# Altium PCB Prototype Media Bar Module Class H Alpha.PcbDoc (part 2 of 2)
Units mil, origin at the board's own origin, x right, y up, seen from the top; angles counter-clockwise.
Board outline 436.13 x 1831.8 mil, 6 copper layers (Component Side, Ground Plane (GND), Inner Layer 1, Inner Layer 2, Power Plane (VCC), Solder Side), stack 51.068 mil thick; 139 components, 72 nets, 710 pads, 418 vias.
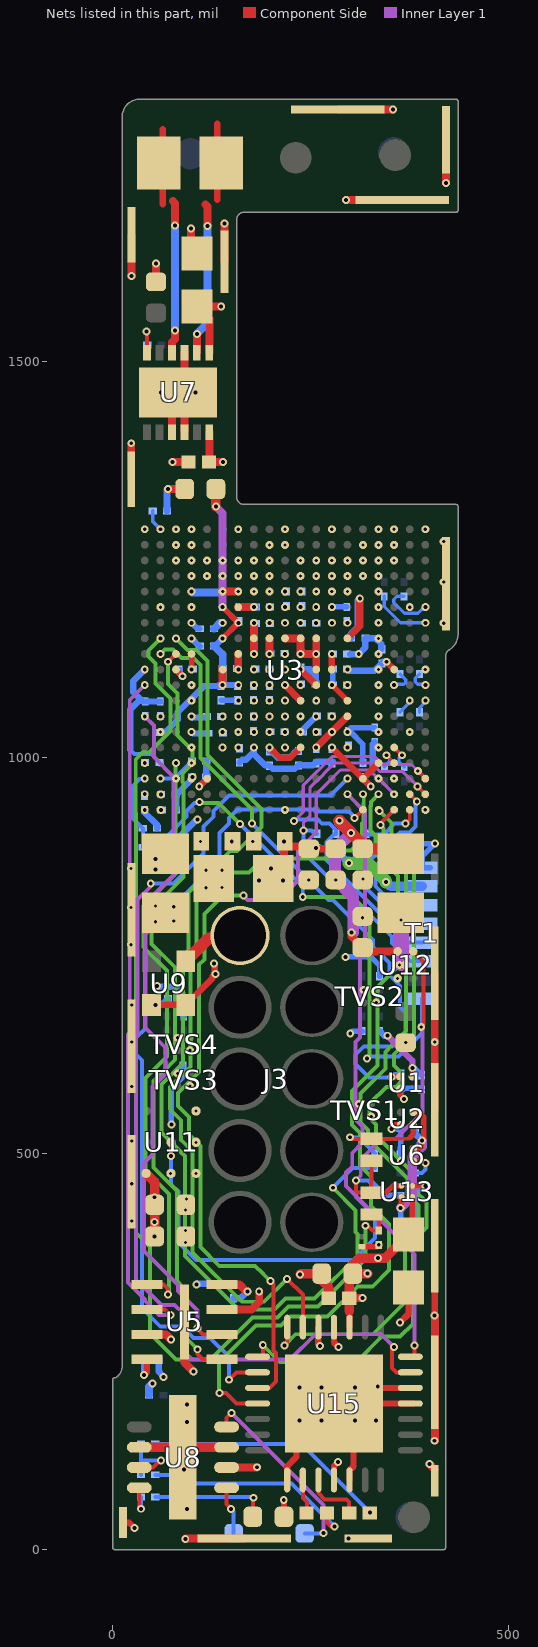
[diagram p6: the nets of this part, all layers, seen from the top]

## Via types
v1: diameter 10, hole 5, Component Side to Solder Side, tented both sides, 279 vias
v2: diameter 10, hole 4, Component Side to Ground Plane (GND), tented both sides, 132 vias
v3: diameter 10, hole 4, Ground Plane (GND) to Inner Layer 1, tented both sides, 6 vias
v4: diameter 10, hole 5, Component Side to Solder Side, 1 vias

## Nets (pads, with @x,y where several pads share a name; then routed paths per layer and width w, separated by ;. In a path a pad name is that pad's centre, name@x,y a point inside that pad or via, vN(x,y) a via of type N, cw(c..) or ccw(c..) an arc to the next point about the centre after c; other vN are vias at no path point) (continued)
GND: C1.1 C2.1 C3.1 C4.1 C5.1 C6.1 C7.1 C8.1 C12.2 C13.2 C14.2 C15.2 C16.1 C17.2 C18.1 C19.1 C20.1 C21.1 C22.1 C23.1 C24.1 C25.1 C26.1 C27.1 C28.1 C29.1 C30.1 C31.1 C32.1 C33.1 C34.1 C35.1 C36.1 C37.1 C38.1 C39.1 C40.1 C41.1 C42.1 C43.1 C44.1 C47.1 C50.1 C51.1 C52.1 C58.1 C59.1 C60.1 C61.1 C62.1 C63.1 C64.1 C65.1 C66.1 C67.1 C68.1 C69.1 C70.1 C71.1 C72.1 C73.1 C77.1 C78.1 C81.1 C82.1 C94.1 C95.1 J3.10 pad.2@12.74,34.06 pad.2@23.38,1351.87 pad.2@23.62,464.31 pad.2@23.62,635.96 pad.2@23.62,808.01 pad.2@23.62,1660.49 pad.2@141.1,1626.52 pad.2@165.9,13.93 pad.2@284.41,1818.88 pad.2@322.99,13.93 pad.2@365.51,1704.7 pad.2@406.69,86.83 pad.2@406.69,211.16 pad.2@406.69,384 pad.2@406.69,555.65 pad.2@406.69,727.7 pad.2@420.64,1219.86 pad.2@421.02,1780.45 R1.1 R2.1 R5.2 R20.1 R21.2 R23.2 R24.2 R25.2 R30.2 R32.2 R33.2 R37.2 R62.2 R67.2 R68.2 T1.1 TVS1.A2 TVS1.B1 TVS2.A2 TVS2.B1 TVS3.A2 TVS3.B1 TVS4.A2 TVS4.B1 TVS7.2 U1.B1 U2.B1 U3.A1 U3.A10 U3.A19 U3.C3 U3.C4 U3.C16 U3.C17 U3.D16 U3.E4 U3.E10 U3.E12 U3.E16 U3.F2 U3.F4 U3.F6 U3.F9 U3.F11 U3.F13 U3.F16 U3.F18 U3.G4 U3.G8 U3.G9 U3.G11 U3.G12 U3.G16 U3.H4 U3.H6 U3.H8 U3.H10 U3.H12 U3.H13 U3.H16 U3.J4 U3.J7 U3.J9 U3.J11 U3.J16 U3.K1 U3.K4 U3.K8 U3.K10 U3.K12 U3.K13 U3.K16 U3.K19 U3.L4 U3.L8 U3.L9 U3.L11 U3.L12 U3.L13 U3.L16 U3.M4 U3.M8 U3.M9 U3.M10 U3.M11 U3.M12 U3.M16 U3.N4 U3.N7 U3.N8 U3.N12 U3.N16 U3.P2 U3.P4 U3.P7 U3.P8 U3.P12 U3.P13 U3.P16 U3.P18 U3.R4 U3.R6 U3.R7 U3.R8 U3.R9 U3.R10 U3.R11 U3.R12 U3.R13 U3.R14 U3.R16 U3.T4 U3.T5 U3.T6 U3.T7 U3.T8 U3.T9 U3.T11 U3.T12 U3.T13 U3.T14 U3.T15 U3.T16 U3.U3 U3.U4 U3.U5 U3.U6 U3.U7 U3.U8 U3.U9 U3.U11 U3.U12 U3.U13 U3.U14 U3.U15 U3.U16 U3.U17 U3.V3 U3.V4 U3.V5 U3.V10 U3.V11 U3.V16 U3.V17 U3.W1 U3.W3 U3.W4 U3.W7 U3.W10 U3.W13 U3.W16 U3.W17 U3.W19 U5.4 U5.9 U6.B1 U7.3 U7.9 U7.10 U7.13 U8.2 U8.7 U8.9 U9.2 U11.B1 U11.C1 U11.C2 U11.C3 U12.A3 U13.B1 U15.8 U15.12 U15.18 U15.19 U15.25 U15.29 | length 3762.9
  Component Side w7: v1(99.51,1111.49) U3.L16@99.51,1131.18 ; U3.J7@276.48,1092 v1(276.67,1091.81) U3.H6@296.36,1072.12 ; TVS7.2@315,382.7 333.76,382.7 v2(336,384.94) ; v1(351.93,531) 357.55,536.62 U2.B1@363.74,536.62 ; U1.B1@362.74,581.62 362.74,574.26 v1(368,569) ; U13.B1@378.51,459.38 v1@394.62,459.38
  Component Side w8: pad.2@12.74,34.06 21.05,34.06 v1(27.62,27.49) ; v1(39.62,220.6) 43.37,224.36 U5.4@43.37,240.25 ; v1(216,62.45) 216.3,62.14 C47.1@216.3,41.49 ; U15.8@220.36,88.04 220.36,105.36 232,117 232,132.07 U15.29@284.42,184.49 ; U15.25@279.42,280.95 279.42,261.58 v1(285,256) ; U15.12@299.1,88.04 299.1,100 304.1,105 304.1,164.81 U15.29@284.42,184.49 ; v1(363,287) 373.62,297.62 C95.1@373.62,331.03 ; U15.18@365.93,184.49 U15.18@375.87,184.49 ; U15.18@381.19,184.49 U15.18@375.87,184.49 ; U15.19@381.19,204.18 U15.19@375.87,204.18 304.1,204.18 U15.29@284.42,184.49 ; pad.2@406.69,384 406.69,295.74 406.94,295.49 407,295.42 pad.2@407,211.16 ; U15.29@284.42,184.49 U15.18@375.87,184.49
  Component Side w10: pad.2@23.38,1351.87 v1(23.38,1397.26) ; v1(23.62,1608.49) pad.2@23.62,1660.49 ; C50.1@54.62,1601.18 v1(54.62,1624.49) ; v1(69.62,1339.49) C60.1@90.93,1339.49 ; U7.9@74.74,1411.3 74.74,1453.62 U7.13@82.62,1461.49 ; v1(75.62,1373.49) C77.1@95.63,1373.49 ; U7.10@90.49,1411.3 90.49,1453.62 U7.13@82.62,1461.49 ; U7.3@90.49,1511.69 90.49,1469.37 U7.13@82.62,1461.49 ; U5.9@90.62,287.49 90.62,236.38 v1(102,225) ; v1@91.93,13.49 92.37,13.93 pad.2@165.9,13.93 pad.2@166.22,13.93 ; v1(98.62,1668.49) 98.62,1647.96 C52.1@109.62,1636.96 ; v2(138.88,1209.92) v2(158.56,1209.92) ; pad.2@141.1,1626.52 v1(141.1,1675.01) ; v1(158.56,1111.49) U3.L13@158.56,1131.18 ; U3.P13@158.56,1190.23 v1(178.25,1190.23) ; v1(178.25,1131.18) U3.M12@178.25,1150.86 v1(178.25,1170.55) ; v1(197.93,1131.18) U3.M11@197.93,1150.86 ; U3.M10@217.62,1150.86 U3.M9@237.3,1150.86 v1(237.3,1131.18) v1(256.99,1131.18) ; U3.K8@256.99,1111.49 v1(256.99,1131.18) ; U3.M8@256.99,1150.86 v1(256.99,1131.18) ; pad.2@284.41,1818.88 v1(354,1818.88) ; v1(294.83,1704.7) pad.2@365.51,1704.7 ; v1(400,108) pad.2@406.69,101.31 ; pad.2@406.69,555.96 pad.2@406.69,555.65 v2(406.69,641) pad.2@406.69,727.7 ; v1@406.93,137.49 407,137.56 407,211.16 406.94,211.23 v1@406.94,295.49 ; v1(421.02,1726.13) pad.2@421.02,1780.45
  Component Side w12: U8.2@29.14,129.29 U8.2@33.5,129.29 U8.2@39.5,129.29 ; U8.2@39.7,129.49 U8.2@39.5,129.29 ; U8.7@137.14,129.29 U8.7@143.74,129.29 ; U8.7@149.53,129.49 U8.7@149.74,129.29 ; U8.7@150.05,129.29 U8.7@149.74,129.29 ; v1@236.93,347.49 237.93,348.49 C43.1@263.93,348.49 264.25,348.49 264.25,339.56 272.94,330.87 C42.1@272.94,317.5 ; U8.2@39.5,129.29 75.82,129.29 U8.9@88.62,116.49 101.41,129.29 U8.7@143.74,129.29 ; U8.7@143.74,129.29 U8.7@149.74,129.29
  Component Side w15: U9.2@92.27,743.05 121.22,772 157.12,772 J3.10@160.76,775.64
  Solder Side w5: 22,1010 27.22,1004.78 48.66,1004.78 59.06,994.39 R30.2@59.06,994
  Solder Side w7: v1(74,537) 74,582.38 88.62,597 R67.2@88.62,611.44 ; v1(99.51,1170.55) 107.05,1163 C28.1@109.94,1163 ; C34.1@136.8,1072.64 C5.1@157.3,1072.64 ; v1(276.67,1091.81) 278,1093.13 278,1111.94 C6.1@277.94,1112 ; v1(276.67,1190.23) 276.99,1190.55 C58.1@295.62,1190.55 ; v1(293.82,748.47) 313.23,748.5 ; v1(300,652) 302.94,654.94 R37.2@315,654.94 ; 313.26,748.47 320.97,748.47 ; C35.1@316,993.65 316,1017 299.45,1033.55 296.62,1033.55 301.13,1038.06 C17.2@331,1038.06 ; 321,748.5 326.25,748.5 337,737.75 R62.2@337,724.06 ; v1@352.42,531.49 C32.1@363.56,531.49 ; C39.1@363.56,499.49 C32.1@363.56,531.49 ; C32.1@363.56,532.44 C32.1@363.56,531.49 ; R32.2@367.06,890 385.49,890 387.22,891.72 v1(407,891.72) 390.62,875.34 T1.1@390.62,861.17 T1.1@401.17,861.17 ; v1(368,569) 364,573 R2.1@364,582.94 388,582.94 C31.1@390,580.94 ; R5.2@381.67,447.49 381.67,448.68 392.05,459.06 392.11,459 v1(395,459)
  Solder Side w8: 22,1010 22,1061 35,1074 ; v1@39.88,220.6 C13.2@39.88,239.49 ; R24.2@40,933.94 40,931.12 56.06,915.07 C14.2@56.06,911 ; v1(40.45,1111.49) 26,1097.04 26,1083 35,1074 ; v1(56,712) 56,711 80,711 88.06,702.94 C8.1@88.06,696 88.06,675.11 R68.2@89.62,673.55 ; R21.2@60,1071.06 R20.1@41,1071.06 37.94,1071.06 35,1074 ; R25.2@80.06,934 80.06,953 C44.1@99.94,972.89 ; v1(99.45,1032.82) 101.66,1030.6 C15.2@115.94,1030.6 ; v1(99.51,1150.86) 109.37,1141 C70.1@109.94,1141 ; v1@100.94,1051 117.95,1051 C18.1@118.94,1052 ; v1(106,335) v1@106.55,335 ; v1@106.55,335.55 C12.2@152.62,335.55 C12.2@152.93,335.55 ; C67.1@160,993.94 163.77,997.72 168.28,997.72 178.25,1007.68 ; v1(178.25,1013.07) 178.25,1007.68 ; v1(178.25,1190.23) 180.3,1190.23 C29.1@180.56,1190.49 ; C73.1@240.14,1032.6 240.14,1035.59 v1(256.99,1052.44) ; C26.1@277.43,994.94 257,994.94 252.5,990.44 C51.1@234.5,990.44 230.06,986 202.14,986 197.9,990.24 192.76,990.24 178.25,1004.75 178.25,1007.68 ; C7.1@300.06,1131 v1(310.68,1131) 319.06,1139.37 C24.1@319.06,1151.1 331.9,1151.1 339,1144 C62.1@339,1137.06 ; C94.1@381.67,413.49 R5.2@381.67,447.49
  Solder Side w9: R33.2@68.67,1311.49 v1@68.67,1338.55
  Solder Side w10: v1(99.51,1209.92) 100.88,1208.55 C71.1@138.62,1208.55 ; C69.1@159.62,1190.55 180.51,1190.55 C29.1@180.56,1190.49
  other v1: 91.62,13.49 298,14 94,51 90,101 406.62,137.49 93.68,161 235.68,163 263.68,163 305.68,163 332.68,163 94,183 236,205 263.68,205 305.68,205 334.68,206 406.62,295.49 236.62,347.49 40.45,934.33 101,976 217.62,1013.07 197.93,1032.75 296.36,1032.75 99.51,1052.44 178.25,1052.44 197.93,1052.44 158.56,1072.12 178.25,1072.12 217.62,1072.12 197.93,1091.81 237.3,1091.81 178.25,1111.49 217.62,1111.49 256.99,1170.55 276.67,1170.55 256.99,1190.23 217.62,1209.92 237.3,1209.92 60.96,1461.49 104.27,1461.49
  other v2: 92,388 92,403 24,415 92,429 93,443 24,462 73,475 105.11,475.12 363.74,490.62 105.11,514.12 24,516 326.49,547.13 105.11,554.12 310.74,562.87 24,585 97.49,585.62 81.74,601.37 97.49,630.62 370,640.32 24,641 81.74,646.37 24,688 332.72,690.81 316.97,706.56 359.77,721.45 23,764 54,793 77,794 315.62,798 23,811 77,812 54,813 117.88,835.88 138,836 247.62,845.81 281.62,845.81 316.16,846.84 118,858 138,858 23,860 110.93,894.49 176.93,894.49 217.62,934.33 394.78,934.33 79.82,973.7 335.73,973.7 355.41,973.7 99.51,993.38 99.51,1013.07 335.73,1013.07 60.14,1032.75 158.56,1032.75 237.3,1032.75 335.73,1032.75 375.1,1032.75 237.3,1052.44 335.73,1052.44 99.51,1072.12 256.99,1072.12 335.73,1072.12 99.51,1091.81 335.73,1091.81 335.73,1111.49 394.78,1111.49 335.73,1131.18 335.73,1150.86 335.73,1170.55 418,1170 60.14,1190.23 99.51,1190.23 335.73,1190.23 375.1,1190.23 178.25,1209.92 197.93,1209.92 256.99,1209.92 276.67,1209.92 296.36,1209.92 335.73,1209.92 418,1222 99.51,1229.6 119.19,1229.6 138.88,1229.6 158.56,1229.6 178.25,1229.6 197.93,1229.6 237.3,1229.6 256.99,1229.6 276.67,1229.6 296.36,1229.6 316.04,1229.6 335.73,1229.6 79.82,1249.29 99.51,1249.29 119.19,1249.29 138.88,1249.29 158.56,1249.29 178.25,1249.29 197.93,1249.29 237.3,1249.29 256.99,1249.29 276.67,1249.29 296.36,1249.29 316.04,1249.29 335.73,1249.29 355.41,1249.29 79.82,1268.97 99.51,1268.97 197.93,1268.97 217.62,1268.97 316.04,1268.97 335.73,1268.97 355.41,1268.97 418,1273 40.45,1288.66 79.82,1288.66 99.51,1288.66 158.56,1288.66 217.62,1288.66 276.67,1288.66 335.73,1288.66 355.41,1288.66 394.78,1288.66
INITN: R26.1 U3.C18 | length 49
  Solder Side w5: v4(60.14,973.7) 77.7,973.7 88,984 ; 88,984.05 R26.1@99.94,996
LOUT: C45.2 U15.9 | length 43.8
  Component Side w5: U15.9@240.05,88.04 240.05,65.32 245.36,60 C45.2@245.36,46.41
NetC45_1: C45.1 R19.1 | length 277.3
  Component Side w5: C45.1@270.92,45.99 270.92,45.68 C45.1@270.61,45.99 270.61,34.07 275.68,29 v1(280,29)
  Solder Side w5: R19.1@53.99,94.49 72.93,94.49 83.93,83.49 225.51,83.49 v1(280,29)
NetC46_1: C46.1 R3.1 | length 306.8
  Solder Side w5: R3.1@53.99,133.49 238.51,133.49 v1(325,47)
NetC47_2: C47.2 R4.1 | length 148.6
  Component Side w5: C47.2@177.25,41.49 177.25,64.81 v1@177.93,65.49
  Solder Side w5: R4.1@53.99,66.49 176.93,66.49 v1@177.93,65.49
  other v1: 177.62,65.49
NetL5_1: L5.1 U12.B2 | length 62.1
  Component Side w10: v2(362,738.49) U12.B2@369.62,738.49
  Inner Layer 1 w20: v3@364,740.49 v3(364,795)
  other v2: 364,795
  other v3: 362,738.49
NetL6_1: L6.1 U7.2 | length 289.9
  Component Side w8: 132,1705 132,1801
  Component Side w10: U7.2@106.24,1511.69 v1(106.24,1535.11) ; 117,1699 119.62,1696.38 v1(119.62,1671.49)
  Solder Side w10: v1(106.24,1535.11) 119.62,1548.49 119.62,1602 v1(119.62,1671.49)
NetL6_2: L6.2 U7.4 | length 289
  Component Side w8: 63,1699 63,1794
  Component Side w10: U7.4@74.74,1511.69 74.74,1524.85 78.62,1528.72 v1(78.62,1539.49) ; 76,1703 78.62,1700.38 v1(78.62,1672.49)
  Solder Side w10: v1(78.62,1539.49) v1(78.62,1672.49)
NetR3_2: R3.2 R19.2 U8.3 | length 89
  Component Side w5: U8.3@39.81,103.7 51,103.7 59.8,112.49 v1(61,112.49)
  Solder Side w5: R19.2@35.88,94.49 35.88,112.49 ; R3.2@35.88,133.49 35.88,112.49 ; v1(61,112.49) 35.88,112.49
NetR4_2: R4.2 U8.4 | length 42.5
  Component Side w5: U8.4@33.5,78.11 33.5,53.92 v1@35.88,51.55
  Solder Side w5: v1@35.88,51.55 R4.2@35.88,66.49
  other v1: 35.56,51.55
NetR21_1: R21.1 U3.G18
  other v1: 60.14,1052.44
NetR23_1: R23.1 U3.B18
  other v1: 61,953.82
NetR24_1: R24.1 U3.B19
  other v1: 40.45,954.01
NetR25_1: R25.1 U3.A18
  other v1: 61,933.82
NetR30_1: R30.1 U3.D19
  other v1: 40.45,993.38
NetR33_1: R33.1 U3.W18 | length 26.8
  Solder Side w5: R33.1@50.56,1311.49 50.56,1298.23 v1(60.14,1288.66)
NetR35_1: R35.1 U6.B2 | length 39.8
  Component Side w7: U6.B2@379.49,490.62 392.38,490.62 v1(395,488)
  Solder Side w5: R35.1@381.67,475.49 390.49,475.49 395,480 v1(395,488)
NetR39_2: R39.2 U7.6 | length 44.5
  Component Side w5: v1(42.62,1538.49) 43.25,1537.86 U7.6@43.25,1511.69
  Solder Side w5: v1(42.62,1538.49) 43.56,1537.55 R39.2@43.56,1521.49
NetU3_A3: U3.A3 U15.28 | length 896.2
  Component Side w5: v1(217,258) 220.36,261.36 U15.28@220.36,280.95 ; v1@337.04,915.96 U3.A3@355.41,934.33
  Inner Layer 2 w5: v1(217,258) 231,272 328.62,272 369,312.38 369,394 386,411 386,434.74 372,448.74 372,468.86 322.28,518.58 322.28,530.1 313,539.38 313,575.94 344.34,607.28 344.34,628.66 352.84,637.16 370.5,654.82 370.5,665 370.5,858.5 342.12,886.88 342.12,910.88
  other v1: 338,915
NetU3_A4: U3.A4 U15.1 | length 971.9
  Component Side w5: U15.1@189.49,245.08 v1(189.49,258.49)
  Inner Layer 2 w5: v1(189.49,258.49) 210.98,237 307.77,237 339.77,269 363,269 379,285 379,389.86 396,406.86 396,439 382,453 382,473 332.28,522.72 332.28,537.04 324.5,544.82 324.5,563.5 345.5,584.5 357.43,584.5 364.5,591.57 364.5,602.18 355.42,611.26 355.42,625.6 380.5,650.68 380.5,680 380.5,862.64 352.12,891.02 352.12,917.96 v1(337.18,932.91)
NetU3_A5: U3.A5 U15.2 | length 1063.8
  Component Side w5: v1@146.93,214.49 156.3,223.86 U15.2@182.96,223.86 U15.2@188.28,223.86 ; v1(305.48,923.9) 305.62,923.9 U3.A5@316.04,934.33
  Solder Side w5: v1(146.62,214.49) 146.62,244 123.12,267.5 101.82,267.5 87.32,282 60,282 37,305 37,618 29.09,625.91 29.09,646.23 40.5,657.63 40.5,776.65 134.61,870.76 134.61,904.9 147,917.29 147,924 157.79,934.79 257,934.79 259.51,932.28 298.25,932.28 305.48,925.06 v1(305.48,923.9)
NetU3_B3: U3.B3 U15.3 | length 1090.6
  Component Side w5: U15.3@182.96,204.18 198.18,204.18 206.21,212.21 206.21,248.28 203,251.49 203,335 v1(199,339)
  Inner Layer 1 w4: 234,883 256.99,905.99 256.99,954.01 287.57,984.6 324.32,984.6 334.2,974.71 ; 334.71,974.71 v2(355.41,954.01)
  Inner Layer 1 w5: v1(165,826) 170.46,820.54 209.54,820.54 234,845 234,883
  Inner Layer 2 w5: v1(165,826) 139,826 115.86,802.86 115.86,745.54 109,738.68 109,603 82.5,576.5 82.5,560.32 96.5,546.32 96.5,524.5 111,510 111,381.93 134.5,358.43 179.57,358.43 189.5,348.5 192,346 v1(199,339)
  other v3: 355.41,954.01
NetU3_B4: U3.B4 U15.4 | length 1024.5
  Component Side w5: v1(135,198) 142.99,198 156.5,184.49 U15.4@182.96,184.49 ; U15.4@182.46,184.99 U15.4@182.96,184.49 ; U15.4@188.28,184.49 U15.4@182.96,184.49
  Inner Layer 2 w5: v1(135,198) 134.12,198.88 134.12,236.35 164.95,267.19 166.88,269.12 180.81,283.05 212.4,283.05 223.86,294.5 271.5,294.5 309,332 328,332 349,353 349,411 326.22,433.78 326.22,471.17 312.28,485.1 312.28,525.96 302,536.24 302,579.08 334.34,611.43 334.34,710.34 360.5,736.5 360.5,850.64 332.12,879.02 332.12,902.12 325.78,908.47 325.78,929 325.78,932.31 325.78,938.9 ; 325.9,939.02 325.9,944.21 v1(335.7,954.01)
NetU3_B5: U3.B5 U15.27 | length 995
  Component Side w5: v1(220,342) 240.05,321.95 U15.27@240.05,280.95
  Inner Layer 2 w5: v1(220,342) 191.05,313.05 163.1,313.05 101,375.14 101,502.86 86.5,517.36 86.5,542.18 72.5,556.18 72.5,584.4 98.5,610.4 98.5,745.36 105.86,752.72 105.86,818.86 142,855 172,855 190,873 282.01,873 291.74,882.73 300.73,882.73 314.6,896.6 314.6,916.9 316.88,919.18 316.88,928.62 316.88,942.59 ; v1(316.04,954.01) 317,953.05 317,942.71
POWER_EN: D3.2 D4.2 R5.1 U11.B2 U12.C1 U13.B2 | length 1005
  Component Side w5: v1(73.62,497) U11.B2@73.62,514.49 ; v1(307,466) 307,453 309.22,450.78 D4.2@327,450.78 ; D3.2@327,491.22 D4.2@327,450.78 ; 345.4,450.78 D4.2@327,450.78 ; U12.C1@379.46,755.54 392.62,742.38 392.62,662.93 v2(389.68,660)
  Component Side w7: 345.4,450.78 354,459.38 U13.B2@364.73,459.38
  Inner Layer 1 w5: v1(307,466) 313.25,472.25 313.25,492.75 339,518.5 357.11,518.5 390.99,552.38 390.99,658.69 v2(389.68,660)
  Solder Side w5: v1(73.62,497) 73.62,461.38 83,452 83,388 105.07,365.93 303.93,365.93 331.5,393.5 331.5,420.5 307,445 v1(307,466) ; v1@308,465 v1(307,466) ; 325,466 v1(307,466)
  Solder Side w7: 325,464.62 326.38,464.62 343.51,447.49 R5.1@363.56,447.49
  other v3: 389.68,660
POWER_HOLD: D4.1 R1.2 U3.M18 | length 1349.7
  Component Side w5: v1(319,409) 321.88,409 327.82,403.06 R1.2@336,403.06 336,414.22 D4.1@327,423.22
  Inner Layer 2 w5: v1(60.14,1150.86) 45,1135.72 45,1128 54,1119 54,1094 73,1075 73,1034 45.6,1006.6 37.55,1006.6 29.05,998.1 29.05,929.6 29.09,929.56 29.09,400.24 47,382.33 47,273 80.01,239.99 123.62,239.99 176.67,293.05 208.26,293.05 222.22,307 259,307 319,367 v1(319,409)
PROGRAM_N: C14.1 R22.2 T1.7 U3.C19 | length 786.5
  Inner Layer 2 w5: v1@109.35,943 133.88,943 v1(160.57,916.3) ; v1(240,824) 303,824 324.34,802.66 324.34,623.34 v1(321,620)
  Solder Side w5: R22.2@37.94,887 37.94,899 ; v1(40.45,973.7) 39.76,973 34,973 25.6,964.6 25.6,923.34 C14.1@37.94,911 37.94,899 ; v1@109,943 103,943 93.5,933.5 93.5,925.95 66.55,899 37.94,899 ; v1(160.57,916.3) 171.28,905.6 172.08,905.6 240,837.68 v1(240,824) ; v1(321,620) 324.01,623.01 361.01,623.01 390.62,652.62 T1.7@390.62,695.82
  other v1: 109.35,944.03
ROUT: C46.2 U15.10 | length 74.6
  Component Side w5: U15.10@259.73,88.04 259.73,71.27 267.51,63.49 295.51,63.49 298.63,60.37 C46.2@298.63,45.99
RX_CLK_N: C90.2 U3.P1 | length 67.2
  Solder Side w4: C90.2@368,1203.94 367.94,1204 359,1204 355,1200 355,1196 368.45,1182.55 385.55,1182.55 393.23,1190.23 v1(394.78,1190.23)
RX_CLK_P: C89.2 U3.N1 | length 75.2
  Solder Side w4: C89.2@343,1203.94 343,1191.03 363.48,1170.55 v1(394.78,1170.55) v1@393.33,1172
RX_N: C88.2 U3.J1 | length 26.8
  Solder Side w4: C88.2@387.62,1105.94 382,1100.33 382,1096 385.13,1092.86 393.73,1092.86 v1(394.78,1091.81)
RX_P: C87.2 U3.J3 | length 29.9
  Solder Side w4: v1(355.41,1091.81) 356.47,1092.86 367.86,1092.86 370,1095 370,1098.56 C87.2@362.62,1105.94
SCL: U3.B6 U15.21 | length 773.2
  Component Side w5: U15.21@380.87,243.55 v1(380.87,257.87)
  Inner Layer 1 w5: v1(296.36,954.01) 318.81,931.56 318.81,772.22 312.5,765.91 312.5,646.82 306.5,640.82 306.5,543.43 315.62,534.32 315.62,514 302.5,500.88 302.5,484 294.5,476 294.5,459.36 380.87,372.98 v1(380.87,257.87)
SDA: U3.C6 U15.20 | length 1310.1
  Component Side w5: v1(355,256) 356,256 352.63,252.63 352.63,229.37 358.14,223.86 U15.20@375.87,223.86 U15.20@380.87,223.86
  Inner Layer 1 w5: v1(48,841) 48,837.28 31.5,820.78 31.5,648.63 29.09,646.23 29.09,633.47 29.09,341.23 61.38,308.95 78.16,308.95 88,299.1 88,252 100,240 224,240 256,272 339,272 v1(355,256)
  Solder Side w5: v1(48,841) 76.56,841 114.61,879.05 114.61,913.19 127,925.58 127,933 146.59,952.59 275.25,952.59 v1(296.36,973.7)
SPI_FLASH_CLK: R20.2 U3.G19 U5.6 | length 884.6
  Component Side w5: v1@107,279 114.26,271.74 U5.6@136.74,271.74
  Inner Layer 1 w5: v1(40.45,1052.44) 51.85,1041.04 51.85,1001.15 77,976 77,852.14 41.5,816.64 41.5,658.82 66.5,633.82 66.5,600.78 50,584.28 50,499 39.43,488.43 39.43,377 82.43,334 82.43,326.66 107,302.09 v1(107,280)
SPI_FLASH_CS_N: U3.D17 U5.1 | length 758.2
  Component Side w5: U5.1@43.37,334.74 64.26,334.74 70,329 v1(70,322)
  Inner Layer 2 w5: v1@71,323 71,449 41.5,478.5 41.5,595.82 68.5,622.82 68.5,731.36 39.09,760.76 39.09,813 79.4,853.31 v1@79.4,992.96
  other v1: 79.82,993.38
SPI_FLASH_MISO: U3.J19 U5.2 | length 856.8
  Component Side w5: U5.2@53.69,303.24 66.18,303.24 v1(72.98,296.45)
  Inner Layer 1 w5: 39.93,314.93 58.39,296.46 v1@72.96,296.46 ; v1(40.45,1091.81) 21.5,1072.85 21.5,653 19.09,650.59 19.09,337.09 40.59,315.59
SPI_FLASH_MOSI: U3.L17 U5.5 | length 1003.5
  Component Side w5: v1(69.98,1121.34) U3.L17@79.82,1131.18 ; v1(107,253) 107,247 113.75,240.25 U5.5@137.86,240.25
  Inner Layer 2 w5: v1(69.98,1121.34) 69.98,1093.02 82,1081 82,1028 101,1009 101,993 88.3,980.3 88.3,969.56 89.4,968.46 89.4,849.17 49.09,808.86 49.09,764.91 78.5,735.5 78.5,618.68 51.5,591.68 51.5,482.64 81,453.14 81,339 89,331 89,271 v1(107,253)
TCK: R32.1 T1.3 U3.B2 | length 217.1
  Component Side w5: U3.B2@375.1,954.01 384,945.11 v1(384,945)
  Solder Side w5: v1@385.11,944 382.12,941.02 382.12,913 374.72,905.6 362.6,905.6 348.94,891.95 R32.1@348.94,890 348.94,880.69 331.63,863.37 331.63,837.78 355.48,813.93 T1.3@390.62,813.93
TDI: R28.2 T1.5 U3.C1 | length 501.6
  Component Side w5: v2@385.4,983.4 U3.C1@394.78,974.01
  Inner Layer 1 w4: v1(229,920) 240.57,931.57 240.57,965.19 277,1001.62 ; 277,1001.67 331.01,1001.67 340.85,991.82 345.69,991.82 ; 346,991.51 377.28,991.51 v3@385.11,983.69
  Solder Side w4: v1(229,920) v1@231,922
  Solder Side w5: v1@231,922 259,922 264,917 274,917 282,909 R28.2@282,904.06 280.05,904.06 270,894 270,871.12 362.96,778.16 362.96,770.32 366.59,766.68 T1.5@390.62,766.68
  other v2: 385.31,983.31
  other v3: 385.31,983.31
TDO: R29.2 T1.6 U3.B1 | length 503.6
  Component Side w4: v1(385.11,963.69) U3.B1@394.78,954.01 ; v1@385.11,964 U3.B1@394.78,954.33
  Inner Layer 1 w4: v1(241,908) 241,918 249,926 249,962 266.28,979.28 266.28,979.72 279.89,993.33 326.76,993.33 337.48,982.61 366.5,982.61 v1@385.11,964
  Solder Side w5: R29.2@258,904.06 254.94,904.06 251,908 v1(241,908) 241,880.28 280.65,840.64 286.34,840.64 352.96,774.02 352.96,766.17 376.07,743.06 T1.6@390.62,743.06
TMS: R27.2 T1.4 U3.A2 | length 236.1
  Component Side w5: v1(370,917) 375.1,922.1 U3.A2@375.1,934.33
  Solder Side w5: R27.2@321,904.06 321.81,903.24 333,903.24 ; v1(370,917) 356.12,917 342.36,903.24 333,903.24 ; T1.4@390.62,790.3 364.96,790.3 321.63,833.63 321.63,867.52 333.5,879.39 333.5,902.74 333,903.24
TX_CLK_N: C86.2 U3.H2 | length 19.7
  Solder Side w4: C86.2@362.62,1057.55 375.1,1070.03 v1(375.1,1072.12)
TX_CLK_P: C85.2 U3.H1 | length 17.5
  Solder Side w4: C85.2@387.62,1057.55 387.62,1063.43 394.78,1070.59 v1(394.78,1072.12)
TX_N: C84.2 U3.E3 | length 33.2
  Component Side w5: U3.E3@355.41,1013.07 v1(365.26,1003.22)
  Solder Side w4: 361.41,995.01 361.41,995.25 ; v1(365.26,1003.22) 361.41,999.38 361.41,995.25 ; C84.2@368.12,988.55 361.41,995.25
TX_P: C83.2 U3.D3 | length 35.4
  Component Side w5: v1(345.57,1003.22) U3.D3@355.41,993.38
  Solder Side w4: C83.2@342.93,988.49 349.41,994.97 ; v1(345.57,1003.22) 349.41,999.38 349.41,994.97 ; 349.41,997.44 349.41,994.97
V1P2: C1.2 C2.2 C18.2 C19.2 C20.2 C21.2 C22.2 C23.2 C24.2 C25.2 C27.2 C28.2 C29.2 C30.2 C33.2 C40.2 C41.2 C78.2 U3.E8 U3.E14 U3.F7 U3.G6 U3.G10 U3.G14 U3.H9 U3.H11 U3.J8 U3.J10 U3.J12 U3.K9 U3.K11 U3.L10 U3.M6 U3.N9 U3.N10 U3.N11 U3.N14 U3.P9 U3.P10 U3.P11 U11.A1 | length 357.4
  Component Side w9: v1@52.93,413.93 v1(53,414) ; C40.2@52.93,435.49 C40.2@53,435.42 ; v1(217.62,1091.81) U3.H9@237.3,1072.12 ; v1(237.3,1111.49) U3.J8@256.99,1091.81 ; v1(256.99,1013.07) v1(276.67,1032.75) U3.G6@296.36,1052.44 ; U3.M6@296.36,1150.86 312,1166.5 v1(312,1201) ; C41.2@51.49,395.49 52,396 52.42,396 v1(52.93,395.49) C41.2@51.49,395.49
  Component Side w12: U11.A1@42.12,475.12 52.93,464.31 C40.2@52.93,435.49 52.93,413.93 v1(52.93,395.49)
  Solder Side w9: v1(237.3,1111.49) 249.51,1111.49 256.06,1104.94 C19.2@256.06,1093 ; C24.2@300.94,1151.1 300.94,1156.18 309.76,1165 309.76,1173.76 310,1174 310,1199 v1(312,1201)
  Solder Side w10: C28.2@128.06,1163 135.6,1170.55 v1(138.88,1170.55)
  other v1: 53,445 54,859 54,872 138.88,1013.07 138.88,1052.44 217.62,1052.44 197.93,1072.12 178.25,1091.81 197.93,1111.49 217.62,1131.18 197.93,1170.55 217.62,1170.55 237.3,1170.55 197.93,1190.23 217.62,1190.23 237.3,1190.23
V2P5: C59.2 C63.2 C64.2 C65.2 C82.2 L5.2 U3.E6 U3.G7 U3.J6 U12.C3 | length 441.5
  Component Side w7: C82.2@316.12,760.81 C82.2@316.62,760.31 ; C82.2@316.62,758.81 C82.2@317.13,758.81
  Component Side w10: v1@301.31,778.7 301.31,774.62 C82.2@315.62,760.31 317.13,758.81 320.39,755.54 U12.C3@359.77,755.54
  Component Side w15: v1(286.56,920.56) 286.56,919.44 v1(301,905) 315.62,890.38 C59.2@315.62,885.18 357.33,885.18 L5.2@363.62,878.89
  Inner Layer 1 w10: v1(301.51,779.51) 301.51,798
  Inner Layer 1 w12: 281,847 281,885 v1(301,905)
  Inner Layer 1 w15: 281,885 280.66,884.66 ; v1@303.81,779.51 303.81,824.19 281,847 280.66,847.34 280.66,884.66 ; 280.66,884.66 v1(301,905) ; v1(301,905) 301,905.18 286.56,919.62 v1(286.56,920.56) 286.56,919.44 v1(301,905)
  other v1: 296.36,1013.07 276.67,1052.44 296.36,1091.81
V3P3: C3.2 C4.2 C5.2 C6.2 C7.2 C8.2 C12.1 C13.1 C15.1 C16.2 C17.1 C26.2 C34.2 C35.2 C36.2 C37.2 C38.2 C42.2 C43.2 C44.2 C51.2 C58.2 C60.2 C61.2 C62.2 C66.2 C67.2 C68.2 C69.2 C70.2 C71.2 C72.2 C73.2 C95.2 R17.1 R22.1 R26.2 R27.1 R28.1 R29.1 R34.2 T1.2 U3.C5 U3.C15 U3.D4 U3.E7 U3.E9 U3.E11 U3.E13 U3.F8 U3.F10 U3.F12 U3.F14 U3.G13 U3.J13 U3.J14 U3.K3 U3.K6 U3.K7 U3.K14 U3.K17 U3.L7 U3.M14 U3.N6 U3.N13 U3.P14 U5.3 U5.7 U5.8 U8.6 U9.1 U9.4 U13.A1 U15.11 U15.24 U15.26 | length 1857.9
  Component Side w7: v1(138.88,1150.86) v1(158.56,1170.55) U3.P14@138.88,1190.23 ; C43.2@303.3,348.49 C43.2@303.62,348.81 ; C43.2@303.62,348.49 C43.2@303.62,348.81 ; C43.2@303.62,349.62 C43.2@303.62,348.81 ; C95.2@373.62,397.96 378.51,402.85 U13.A1@378.51,445.6
  Component Side w8: v1(54,687.93) U9.1@92.27,687.93 126,721.66 126,724 127,725 129,725 129,739 v1(128,740) ; U3.K17@79.82,1111.49 79.82,1111.18 v1(88,1103) ; v1@108.83,963.33 v1(109.28,963.78) U3.C15@119.19,973.7 115,969.5 ; v1(197.93,1013.07) 210.83,1000.17 224.4,1000.17 U3.E9@237.3,1013.07 ; U15.26@259.73,280.95 259.73,259.27 v1(262,257) ; v1(276.67,1013.07) 308.87,980.87 308.87,980.81 v1@325.93,963.76 ; U3.K7@276.67,1111.49 v1(276.67,1131.18) ; U15.11@279.42,88.04 279.42,105.42 v1(284.42,110.42) v1@285,111 ; C42.2@298.61,317.5 298.92,317.5 C43.2@298.92,343.8 ; 298.92,301 298.92,281.13 U15.24@299.1,280.95 ; v1(325.86,963.88) U3.C5@316.04,973.7 U3.D4@335.73,993.38 ; v1(345.57,1121.34) U3.K3@355.41,1111.49
  Component Side w10: U5.3@43.37,271.74 67.35,271.74 v1(73.71,265.38) ; U5.7@137.86,303.24 175.37,303.24 178.62,306.49 185,312.87 185,320 v1(185,326) ; U5.8@137.86,334.74 160,334.74 168.74,326 v1(170,326) ; v1(138.88,1091.81) U3.K14@138.88,1111.49 ; U8.6@149.74,103.7 181.7,103.7 v1(182,104) ; C38.2@216.3,862.28 v1(216.3,894.49) ; C37.2@222.79,888 244.79,888 C61.2@247.62,885.18 C72.2@281.62,885.18 ; C42.2@298.92,317.5 v1(315.5,317.5)
  Component Side w12: v1(130.3,1317.18) C60.2@130.3,1339.49 ; 298.92,301 298.92,317.5 298.92,344.11 C43.2@303.3,348.49 ; C43.2@303.62,349.62 C43.2@303.3,349.3 ; v1(321.93,348.49) 303.62,348.49 C43.2@303.3,348.49 ; C95.2@373.62,397.96 373.62,397.56 344.06,368 v1(335,368) 311,368 303.3,360.3 C43.2@303.3,349.3 ; C43.2@303.3,348.49 C43.2@303.3,349.3
  Inner Layer 1 w10: v1(130.3,1317.18) 138.62,1308.86 v1(138.62,1190.44)
  Inner Layer 2 w16: v1(298.16,867.23) 298.89,866.5 322.72,866.5 345,844.22 v1(345,843)
  Solder Side w6: C34.2@136.8,1090.76 138.04,1092 138.94,1092.9 v1@138.94,1095.89
  Solder Side w8: v1(54,687.93) 61.88,687.93 C8.2@69.94,696 ; R22.1@56.06,887 71,887 71,887.18 105.82,922 v1(107,922) ; 57.99,225 C13.1@57.99,239.49 ; 58,225 v1@64,219 ; R34.2@58.06,1033 67,1033 82.1,1048.1 82.1,1057.34 115.51,1090.76 C34.2@136.8,1090.76 ; C3.2@84.94,1111 84.94,1106.06 v1(88,1103) ; v1(109.28,963.78) 118.06,972.56 C44.2@118.06,976 ; C44.2@118.06,978 C44.2@118.06,976 ; R26.2@118.06,996 C44.2@118.06,976 ; C70.2@128.06,1141 129.02,1141 v1(138.88,1150.86) ; C34.2@138.04,1092 C5.2@156.06,1092 ; C12.1@152.93,317.44 161.44,317.44 v1(170,326) ; C66.2@197.9,1008.36 200.41,1008.36 208.6,1000.17 223.6,1000.17 231.99,1008.56 C51.2@234.5,1008.56 ; C6.2@300.06,1110.1 330.15,1110.1 C62.2@339,1118.94 ; v1@325.93,963.76 316,973.68 C35.2@316,975.54 318.51,975.54 328.23,985.26 328.23,1017.18 C17.1@331,1019.94 ; C62.2@341.39,1121.34 v1(345.57,1121.34)
  Solder Side w9: R28.1@282,885.94 282,883.39 v1(298.16,867.23) 301.29,867.23 R27.1@320,885.94
  Solder Side w10: R17.1@45.94,195 45.94,205.72 v1@49.61,209.39 ; C70.2@128.06,1141 138.94,1130.11 C4.2@138.94,1113 v1@138.94,1095.89
  Solder Side w12: v1@345.25,843.25 350.95,837.55 T1.2@390.62,837.55
  other v1: 50.11,209.89 64,218 130,727 185,845 215,845 200,860 257,886 150.3,894.49 158.56,1013.07 138.88,1032.75 178.25,1032.75 217.62,1032.75 256.99,1032.75 158.56,1052.44 158.56,1091.81 296.36,1111.49 296.36,1170.55
V3P3_ALWAYS: C31.2 C32.2 C39.2 C52.2 C77.2 C94.2 R15.2 U1.A2 U2.A2 U6.A2 U7.1 U7.12 U13.A2 | length 477
  Component Side w7: v1@364.73,432.6 U13.A2@364.73,445.6 ; U1.A2@378.49,597.37 v1(378.49,608) ; U6.A2@379.49,506.37 386.73,506.37 390.37,510 390.37,516.15 v1(390.69,516.47) ; U2.A2@379.49,552.37 386.74,552.37 392.91,546.2 392.91,519.79 v1@390.14,517.02 ; v1@390.37,516.47 390.37,516.79 v1@391.56,517.99
  Component Side w10: U7.12@121.99,1411.3 122.24,1411.04 122.24,1374.12 C77.2@121.61,1373.49 v1(139,1373.49) ; U7.1@121.99,1511.69 121.99,1554.66 C52.2@106.62,1570.03 v1(137,1570.03)
  Inner Layer 1 w8: v1(347,649) 378.49,617.51 v1(378.49,608)
  Inner Layer 1 w12: v1(363.62,431.49) 378,445.87 378,496.25 390.69,508.94 v1(390.69,516.47)
  Solder Side w7: C94.2@363.56,413.49 363.56,431.44 v1(363.62,431.49) ; v1(378.49,608) 381.06,608 C31.2@390,599.06 ; C39.2@381.67,499.49 381.67,507.46 v1(390.69,516.47)
  Solder Side w8: R15.2@337,654.94 342.94,649 v1(347,649) ; C32.2@381.67,531.49 381.67,525.49 v1(390.69,516.47)
VO+: T2.1 U8.5 | length 61.3
  Component Side w5: U8.5@143.74,78.11 143.74,57.37 v1(149.62,51.49)
  Solder Side w5: v1(149.62,51.49) 152.74,48.37 T2.1@152.74,20.49
VO-: T2.2 U8.8 | length 243.5
  Component Side w5: U8.8@143.74,154.88 143.74,166.49 v1(149.74,172.49)
  Inner Layer 1 w5: v1(149.74,172.49) 266,56.23 v1(266,21)
  Solder Side w5: T2.2@242.5,20.49 265.49,20.49 v1(266,21)
WAKE_RX: R7.2 U3.M17 | length 1337.7
  Inner Layer 2 w5: v1(79.82,1150.86) 94.68,1136 106,1136 119.9,1122.1 119.9,1003.69 188,935.59 188,912.88 157.11,881.99 147.99,881.99 95.86,829.86 95.86,756.86 88.5,749.5 88.5,614.54 61.5,587.54 61.5,526.8 86.12,502.18 86.12,501.74 91,496.86 91,371 158.95,303.05 204.12,303.05 218.07,317 254.86,317 309,371.14 309,398.82 306.5,401.32 306.5,428.5 v1(278,457)
  Solder Side w5: v1(278,457) 278,457.17 302.77,481.94 R7.2@331,481.94
WAKE_RX_PWR: D3.1 R7.1 U2.B2 | length 139.6
  Component Side w5: v1(299.78,520.78) 301.78,518.78 D3.1@327,518.78 ; D3.1@327.28,518.5 357.11,518.5 357.48,518.87 373.99,518.87 379.49,524.37
  Component Side w7: 376.06,520.94 379.49,524.37 U2.B2@379.49,536.62
  Solder Side w5: v1(299.78,520.78) 310.28,520.78 R7.1@331,500.06
WAKE_TX: R2.2 U1.A1 U3.L18 | length 796.3
  Component Side w7: v1(352,597) U1.A1@362.38,597
  Inner Layer 2 w5: v1(60.14,1131.18) 65.96,1137 76,1137 87,1126 102,1126 111,1117 111,1000 176,935 v1(176,917)
  Solder Side w5: v1(176,917) 272.36,820.64 278.05,820.64 329,769.69 329,761.3 349.5,740.8 349.5,725.41 362.81,712.1 362.81,685.45 370,678.27 370,652.51 353,635.51 317.01,635.51 306.5,625 306.5,613.5 323.5,596.5 351.5,596.5 v1(352,597) 355.55,600.55 R2.2@360.62,600.55
pads on no net: FD14_4_1.0 FD14_4_2.0 FD14_4_3.0 FD14_4_4.0 FD14_4_5.0 FD14_4_6.0 U3.A7 U3.A8 U3.A9 U3.A11 U3.A12 U3.A13 U3.A14 U3.A15 U3.A16 U3.A17 U3.B7 U3.B8 U3.B9 U3.B10 U3.B11 U3.B12 U3.B13 U3.B14 U3.B15 U3.B16 U3.B17 U3.C2 U3.C7 U3.C8 U3.C9 U3.C10 U3.C11 U3.C12 U3.C13 U3.C14 U3.D1 U3.D2 U3.D18 U3.E1 U3.E2 U3.E17 U3.E18 U3.F1 U3.F3 U3.F17 U3.F19 U3.G1 U3.G2 U3.G3 U3.G17 U3.H3 U3.H7 U3.H14 U3.H17 U3.H18 U3.H19 U3.J2 U3.J17 U3.J18 U3.K2 U3.K18 U3.L1 U3.L2 U3.L3 U3.L6 U3.L14 U3.L19 U3.M1 U3.M2 U3.M3 U3.M7 U3.M13 U3.N2 U3.N3 U3.N17 U3.N19 U3.P3 U3.P6 U3.P17 U3.P19 U3.R1 U3.R2 U3.R3 U3.R17 U3.R18 U3.R19 U3.T1 U3.T2 U3.T3 U3.T10 U3.T17 U3.T18 U3.T19 U3.U1 U3.U2 U3.U10 U3.U18 U3.U19 U3.V1 U3.V2 U3.V6 U3.V7 U3.V8 U3.V9 U3.V12 U3.V13 U3.V14 U3.V15 U3.V18 U3.V19 U3.W2 U3.W5 U3.W6 U3.W8 U3.W9 U3.W11 U3.W12 U3.W14 U3.W15 U7.8 U15.5 U15.6 U15.7 U15.13 U15.14 U15.15 U15.16 U15.17 U15.23

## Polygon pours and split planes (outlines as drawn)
V1P2 on Inner Layer 2 "Top Solder-No Net" (solid, remove dead copper, pour order 15): 129,1009 129,1203 139,1213 143,1217 254,1217 308,1217 322,1203 322,1172 294,1144 258,1108 258,1072 258,1047 263,1042 266,1039 279,1039 286,1032 286,1030 286,1010 278,1002 134,1002 132,1004
V3P3_ALWAYS on Inner Layer 2 "TopLayer-No Net" (solid, remove dead copper, pour order 11): 396,504 396,505 408,517 408,877 397,888 397,904 408,915 408,1266 382,1292 148,1292 136,1304 136,1358 144,1366 144,1576 137,1583 105,1583 71,1549 71,1262 107,1226 317,1226 331,1212 331,1161 313,1143 313,1111 335,1089 335,951 361,925 361,892 386,867 386,646 365,625 365,612.24 372,605.24 370.78,604.02 370.78,509.22 376,504
V2P5 on Inner Layer 2 "TopLayer-No Net" (solid, remove dead copper, pour order 10): 306,1099 320,1085 320,940 309,929 309,918 331,896 331,885.18 326,880 296,880 259,916 252,923 253,924 253,968 291,1006 291,1038 283,1046 273,1046 266,1053 266,1096 269,1099
V3P3 on Component Side "TopLayer-No Net" (solid, remove dead copper, pour order 12): 117,746 131,746 135,742 135,730 135,722 121,708 110,697 110,682 110,677 106,673 43,673 39.15,673 37.15,675 37.15,698 37.15,701.15 39,703 41,705 57,705 87,705 109,727 110,728 110,741 110,743 111,744 113,746 117,746
BAT+ on Component Side "TopLayer-No Net" (solid, remove dead copper, pour order 9): 100,544 109,544 124,559 139,559 143,555 143,544 104,505 39,505 33,511 33,554 47,568 76,568
GND on Ground Plane (GND) (split plane): 33.94,1821.72 33.94,1821.11 34.01,1821.08 34.01,1821.72 426.05,1821.72 426.05,1699.06 165.92,1699.06 165.91,1699.06 165.9,1699.06 165.9,1699.07 165.9,1699.7 165.83,1699.67 165.83,1699.06 162.12,1698.7 158.48,1697.59 155.13,1695.8 152.19,1693.39 149.78,1690.45 147.99,1687.1 146.88,1683.46 146.51,1679.68 146.52,1679.68 146.52,1329.29 146.51,1329.29 146.88,1325.5 147.99,1321.87 149.78,1318.52 152.19,1315.58 155.13,1313.17 158.48,1311.37 162.12,1310.27 165.9,1309.9 426.05,1309.9 426.05,1155.66 426.07,1155.47 425.86,1153.29 425.17,1151.01 424.04,1148.91 422.53,1147.06 420.69,1145.55 419.99,1145.18 419.99,1145.17 419.62,1144.89 418.91,1144.51 415.97,1142.1 413.56,1139.16 411.77,1135.8 410.66,1132.17 410.29,1128.38 410.3,1128.38 410.3,10.09 10.09,10.09 10.09,209.23 10.66,209.58 13.91,212.36 16.69,215.61 18.92,219.26 20.56,223.21 21.56,227.37 21.89,231.59 21.9,231.63 21.9,1809.6 21.87,1809.8 22.09,1811.97 22.78,1814.26 23.9,1816.36 25.41,1818.2 27.26,1819.71 29.36,1820.84 31.64,1821.53 33.79,1821.74
V1P2 on Power Plane (VCC) (split plane): 241.52,1060.6 228.51,1047.59 190.73,1047.59 173.1,1065.22 173.1,1102.05 172.71,1104.01 171.6,1105.66 157.66,1119.6 156.01,1120.71 154.05,1121.1 86,1121.1 84.05,1120.71 82.4,1119.6 73.4,1110.6 72.29,1108.95 71.9,1107 71.9,1077 72.29,1075.05 73.4,1073.4 87.9,1058.89 87.9,904 88.29,902.05 89.4,900.4 96.9,892.89 96.9,742 97.29,740.05 98.4,738.4 121.9,714.89 121.9,634.11 68.4,580.6 67.29,578.95 66.9,577 66.9,375.11 57.38,365.59 21.9,365.59 21.9,1206.39 241.52,1206.39
BAT+ on Power Plane (VCC) (split plane): 33.94,1821.72 33.94,1821.11 34.01,1821.08 34.01,1821.72 426.05,1821.72 426.05,1699.06 165.92,1699.06 165.91,1699.06 165.9,1699.06 165.9,1699.07 165.9,1699.7 165.83,1699.67 165.83,1699.06 162.12,1698.7 158.48,1697.59 155.13,1695.8 152.19,1693.39 149.78,1690.45 147.99,1687.1 146.88,1683.46 146.51,1679.68 146.52,1679.68 146.52,1329.29 146.51,1329.29 146.88,1325.5 147.99,1321.87 149.78,1318.52 152.19,1315.58 155.13,1313.17 158.48,1311.37 162.12,1310.27 165.9,1309.9 426.05,1309.9 426.05,1155.66 426.07,1155.47 425.86,1153.29 425.17,1151.01 424.04,1148.91 422.53,1147.06 420.69,1145.55 419.99,1145.18 419.99,1145.17 419.62,1144.89 418.91,1144.51 415.97,1142.1 413.56,1139.16 411.77,1135.8 410.66,1132.17 410.29,1128.38 410.3,1128.38 410.3,385.72 332.62,385.72 330.67,385.33 329.01,384.22 308.38,363.59 230.73,363.59 211.1,383.22 211.1,430.89 232.11,451.9 283,451.9 284.95,452.29 286.6,453.4 311.71,478.51 312.82,480.16 313.21,482.11 313.21,506.11 313.21,507.89 335.6,530.29 336.71,531.94 337.1,533.89 337.1,758.89 337.1,758.9 338.21,760.55 338.6,762.5 338.6,1171.61 338.21,1173.56 337.1,1175.21 297.22,1215.1 295.57,1216.2 293.62,1216.59 21.9,1216.59 21.9,1809.6 21.87,1809.8 22.09,1811.97 22.78,1814.26 23.9,1816.36 25.41,1818.2 27.26,1819.71 29.36,1820.84 31.64,1821.53 33.79,1821.74
V3P3 on Power Plane (VCC) (split plane): 328.4,1169.5 328.4,764.61 328.4,764.6 327.29,762.95 326.9,761 326.9,536 304.51,513.6 303.4,511.95 303.01,510 303.01,506.11 303.01,484.22 280.89,462.1 230,462.1 228.05,461.71 226.4,460.6 202.4,436.6 201.29,434.95 200.9,433 200.9,381.11 201.29,379.16 202.4,377.51 225.01,354.89 226.67,353.78 228.62,353.39 310.49,353.39 312.44,353.78 314.1,354.89 334.73,375.52 410.3,375.52 410.3,10.09 10.09,10.09 10.09,209.23 10.66,209.58 13.91,212.36 16.69,215.61 18.92,219.26 20.56,223.21 21.56,227.37 21.89,231.59 21.9,231.63 21.9,355.39 59.49,355.39 61.44,355.78 63.1,356.89 75.6,369.4 76.71,371.05 77.1,373 77.1,574.89 130.6,628.4 131.71,630.05 132.1,632 132.1,717 131.71,718.95 130.6,720.6 107.1,744.11 107.1,895 106.71,896.95 105.6,898.6 98.1,906.11 98.1,1061 97.71,1062.95 96.6,1064.6 82.1,1079.11 82.1,1104.89 88.11,1110.9 151.94,1110.9 162.9,1099.94 162.9,1063.11 163.29,1061.16 164.4,1059.51 185.01,1038.89 186.67,1037.78 188.62,1037.39 230.62,1037.39 232.57,1037.78 234.22,1038.89 250.22,1054.89 251.33,1056.54 251.72,1058.49 251.72,1206.39 291.51,1206.39

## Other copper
Component Side:
  text "Top" at 87,-411 h60
Inner Layer 1:
  text "SIG1_LAYER3" at -113,-415 h60
Inner Layer 2:
  text "SIG2_LAYER4" at -110,-417 h60
Solder Side:
  text "Bottom" at 3,-422 h60
Ground Plane (GND) (plane layer: these items are gaps in the copper):
  text "GND_LAYER2" at -109.38,-426.51 h60
Power Plane (VCC) (plane layer: these items are gaps in the copper):
  lines w10: 8.62,360.49 59.49,360.49 72,373 72,577 127,632 127,717 102,742 102,895 93,904 93,1061 77,1077 77,1107 86,1116 154.05,1116 168,1102.05 168,1063.11 188.62,1042.49 230.62,1042.49 246.62,1058.49 246.62,1211.49 ; 8.62,1211.49 293.62,1211.49 333.5,1171.61 333.5,762.5 332,761 332,533.89 308.11,510 308.11,506.11 308.11,482.11 283,457 230,457 206,433 206,381.11 228.62,358.49 310.49,358.49 332.62,380.62 422,380.62
  text "PWR_LAYER5" at -109.38,-426.51 h60

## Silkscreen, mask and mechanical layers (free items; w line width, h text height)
Top Overlay:
  text "A" at 301,524 h10
  text "K" at 296,473 h10
  text "K" at 302,450 h10
  text "A" at 301,417 h10
  text "Top Overlay" at -92,-376 h60
Bottom Overlay:
  text "M" at 293,1776 h50
  text "Media Bar" at 303,1744 h20
  text "Rev: 1.0" at 301,1714 h20
  text "-" at 241,42 h10
  text "+" at 131,38 h10
  text "Bottom Overlay" at -150,-372 h60
Top Paste:
  text "Top Paste" at -59,-417 h60
Bottom Paste:
  text "Bottom Paste" at -90,-420 h60
Top Solder:
  text "Top Solder" at -67,-417 h60
Bottom Solder:
  text "Bottom Solder" at -87,-417 h60
OUTLINE:
  lines w1: 34.03,1831.8 ccw(c34.01,1829.29) 34.01,1831.8 ; 34.01,1831.8 ccw(c34.01,1809.6) 11.81,1809.6 11.81,231.63 cw(c-5.36,231.63) 3.47,216.91 ccw(c2.51,214.59) 0,214.59 0,2.51 ccw(c2.51,2.51) 2.51,0 417.87,0 ccw(c417.87,2.51) 420.38,2.51 420.38,1128.38 ; 34.01,1831.8 433.62,1831.8 cw(c433.62,1829.29) 436.13,1829.29 436.13,1691.49 cw(c433.62,1691.49) 433.62,1688.98 165.92,1688.98 ; 34.01,1831.8 34.01,1831.8 ; 34.01,1831.8 34.03,1831.8 ; 165.9,1688.98 ccw(c165.9,1679.68) 156.6,1679.68 156.6,1329.29 ccw(c165.9,1329.29) 165.9,1319.99 433.62,1319.99 cw(c433.62,1317.48) 436.13,1317.48 436.13,1155.66 cw(c413.93,1155.66) 425.03,1136.44 ; 165.9,1688.98 ccw(c165.9,1691.49) 165.92,1688.98 ; 420.38,1128.38 cw(c429.68,1128.38) 425.03,1136.44 ; 420.38,1128.38 420.38,1128.38 ; 425.03,1136.44 425.03,1136.44
ASSY_TOP:
  text "ASSY TOP" at -18,-582 h60
ASSY_BOT:
  text "ASSY BOTTOM" at 524,-582 h60
Mechanical 8:
  circle w5: c249.31,774.3 r32.48
  circle w5: c249.31,683.75 r32.48
  circle w5: c249.31,593.2 r32.48
  circle w5: c249.31,502.64 r32.48
  circle w5: c249.31,412.09 r32.48
  circle w5: c158.76,774.3 r32.48
  circle w5: c158.76,683.75 r32.48
  circle w5: c158.76,593.2 r32.48
  circle w5: c158.76,412.09 r32.48
  circle w5: c158.76,502.64 r32.48
  rectangle: 26.62,-631.43 380.95,-1.51
  lines w10: 34.03,1831.8 ccw(c34.01,1829.29) 34.01,1831.8 ; 34.01,1831.8 ccw(c34.01,1809.6) 11.81,1809.6 11.81,231.63 cw(c-5.36,231.63) 3.47,216.91 ccw(c2.51,214.59) 0,214.59 0,2.51 ccw(c2.51,2.51) 2.51,0 417.87,0 ccw(c417.87,2.51) 420.38,2.51 420.38,1128.38 ; 34.01,1831.8 433.62,1831.8 cw(c433.62,1829.29) 436.13,1829.29 436.13,1691.49 cw(c433.62,1691.49) 433.62,1688.98 165.92,1688.98 ; 34.01,1831.8 34.01,1831.8 ; 34.01,1831.8 34.03,1831.8 ; 165.9,1688.98 ccw(c165.9,1679.68) 156.6,1679.68 156.6,1329.29 ccw(c165.9,1329.29) 165.9,1319.99 433.62,1319.99 cw(c433.62,1317.48) 436.13,1317.48 436.13,1155.66 cw(c413.93,1155.66) 425.03,1136.44 ; 165.9,1688.98 ccw(c165.9,1691.49) 165.92,1688.98 ; 420.38,1128.38 cw(c429.68,1128.38) 425.03,1136.44 ; 420.38,1128.38 420.38,1128.38 ; 425.03,1136.44 425.03,1136.44
  text "speaker (9 x 16 x 3 mm)" at -1365.38,269.49 h60
Mechanical 13:
  circle w5: c160.76,503.99 r32.48
  circle w5: c160.76,413.43 r32.48
  circle w5: c160.76,594.54 r32.48
  circle w5: c160.76,685.09 r32.48
  circle w5: c251.31,413.43 r32.48
  circle w5: c251.31,503.99 r32.48
  circle w5: c251.31,594.54 r32.48
  circle w5: c251.31,685.09 r32.48
  circle w5: c251.31,775.64 r32.48
  circle w5: c160.76,775.64 r32.48
Drill Drawing:
  lines w6: -2522.47,2743.38 -2522.47,3496.66 cw(c-2482.8,3496.66) -2482.8,3536.33 113.53,3536.33 cw(c113.53,3502.33) 147.53,3502.33 ; -2522.47,2745.33 ccw(c-2488.47,2745.33) -2488.47,2711.33 ; -2492,2711.33 103,2710.65 ; -2463.69,3343.65 86.31,3343.65 ; -2459,3443 91,3443 ; 101.01,2710.65 ccw(c101.01,2756.89) 147.25,2756.89 ; 147.53,2756.89 147.53,3501.33
  text "FAB NOTES:" at 1521.94,3483.48 h60
  text "6 Layers Stack Up" at -1718,3468 h57
  text "Layer" at -2459,3403 h24
  text "Gerber" at -1559,3403 h24
  text "Copper" at -899,3403 h24
  text "Dielectric" at -399,3403 h24
  text "Name" at -2459,3363 h24
  text "Document" at -1559,3363 h24
  text "Thickness" at -899,3363 h24
  text "Material" at -399,3363 h24
  text "1. Materials: Green clad, FR-4/Epoxy class,or equivalent.dielectric costant 4.2+/-0.2 ," at 1629.62,3337.49 h60
  text "Top Solder Mask" at -2459,3283 h34
  text "(.GTS)" at -1559,3283 h34
  text "0.5mil" at -759,3283 h34
  text "Solder Resist" at -399,3283 h34
  text "see cross section for board thickness, copper" at 1789.62,3217.49 h60
  text "Top" at -2459,3203 h34
  text "(.GTL)" at -1559,3203 h34
  text "1.58mil" at -1039,3203 h34
  text "3.5mil" at -759,3163 h34
  text "FR4" at -399,3163 h34
  text "GND_IN2" at -2459,3123 h34
  text "(.GP1)" at -1559,3123 h34
  text "0.65mil" at -1039,3123 h34
  text "weight and layer structures." at 1789.62,3097.49 h60
  text "2.5mil" at -759,3083 h34
  text "FR4" at -399,3083 h34
  text "SIG1_IN3" at -2459,3043 h34
  text "(.G1)" at -1559,3043 h34
  text "0.65mil" at -1039,3043 h34
  text "2.5mil" at -759,3003 h34
  text "FR4" at -399,3003 h34
  text "2. Components on the top and bottom layers." at 1609.62,2977.49 h60
  text "SIG2_IN4" at -2459,2963 h34
  text "(.G2)" at -1559,2963 h34
  text "0.65mil" at -1039,2963 h34
  text "2.5mil" at -759,2923 h34
  text "FR4" at -399,2923 h34
  text "PWR_IN5" at -2459,2883 h34
  text "(.GP2)" at -1559,2883 h34
  text "0.65mil" at -1039,2883 h34
  text "3. Minimum signal trace width/spacing : 4/3.9 mils." at 1609.62,2857.49 h60
  text "3.5mil" at -759,2843 h34
  text "FR4" at -399,2843 h34
  text "Bottom" at -2459,2803 h34
  text "(.GBL)" at -1559,2803 h34
  text "1.58mil" at -1039,2803 h34
  text "4. Drilling:" at 1609.62,2737.49 h60
  text "Bottom Solder Mask" at -2459,2723 h34
  text "(.GBS)" at -1559,2723 h34
  text "0.5mil" at -759,2723 h34
  text "Solder Resist" at -399,2723 h34
  text "4.1  minimum hole size is 4 mils drill." at 1769.62,2617.49 h60
  text "Overall Thickness :21.26 mil+/-10%" at -2050,2574 h50
  text "4.2  all plated holes are to be plated thru and with min .001 thick." at 1769.62,2497.49 h60
  text "4.3  all hole diameters are finished sizes." at 1769.62,2377.49 h60
  text "4.4  all holes to be +/-0.003 from true position unless" at 1769.62,2257.49 h60
  text "unit:mils" at -574,2208 h63
  text "otherwise specified for PTH, or +/-0.002 if it's NPTH." at 1989.62,2157.49 h60
  text "4.5  NC drill file has been supplied, see hole size table." at 1769.62,2037.49 h60
  text "5. Front to back pattern shall register within .005\"." at 1609.62,1917.49 h60
  text "6. Layer to layer(pattern to pattern) registration to be +/-.005\"." at 1609.62,1797.49 h60
  text "7. Soldermask: Both sides of board, Liquid Photo Imageable, soldermask" at 1609.62,1677.49 h60
  text "over bare copper (SMOBC), green." at 1780.62,1552.49 h60
  text "8. Warpage and twist to meet IPC class II." at 1609.62,1437.49 h60
  text "9. Silkscreen using white non-conductive epoxy or eqv." at 1609.62,1317.49 h60
  text "10. Finish:" at 1569.62,1177.49 h60
  text "10.1  Edge to be free of loose sliver and rough edge." at 1769.62,1057.49 h60
  text "10.2  Finished board shall not have nicks scratches, voids," at 1769.62,937.49 h60
  text "exposed copper, poor plating or misdrilled holes." at 2100.62,832.49 h60
  text "10.3  Trace width tol=+/-.001\" of finished trace width." at 1769.62,717.49 h60
  text "11. Date code and UL rating shall be permanently marked or etched on PCB." at 1569.62,597.49 h60
  text "12. Remove non-functional pad on all inner layers and planes" at 1569.62,477.49 h60
  text "13. Impedance control:" at 1570.62,332.49 h60
  text "13.1 Differential pairs:" at 1780.62,192.49 h60
  text "4/8 mils width/gap on top and bottom and sig1 layers should be controlled 100 ohms +/- 10% ." at 1799.62,47.49 h60
  text "13.2 Single ended signals:" at 1800.62,-102.51 h60
  text "5 mils width on all layer should be controlled 50 ohms +/-10% ." at 1878.62,-249.51 h60
  text "14. Via-in-pad: All 4 & 5mils vias are to be filled with non-conductive expoy and plated over." at 1568.62,-382.51 h60
  text "FAB DRAWING" at -184,-438 h75
  text "15. 4/10 mils (drill/pad) blind/buried vias apply to layer1~2 and layer2~3." at 1582,-539 h60
  text ".Legend" at -2191,-1389 h60

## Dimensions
2.51,0 to 0,214.59 on Drill Drawing
0,214.59 to 11.81,231.63 on Drill Drawing
421.62,1131.49 to 506.62,1047.49 on Drill Drawing
417.87,2.51 to 503.28,-83.54 on Drill Drawing
435,1146 to 623.69,1187.83 on Drill Drawing
10.62,227.49 to -181.38,415.49 on Drill Drawing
